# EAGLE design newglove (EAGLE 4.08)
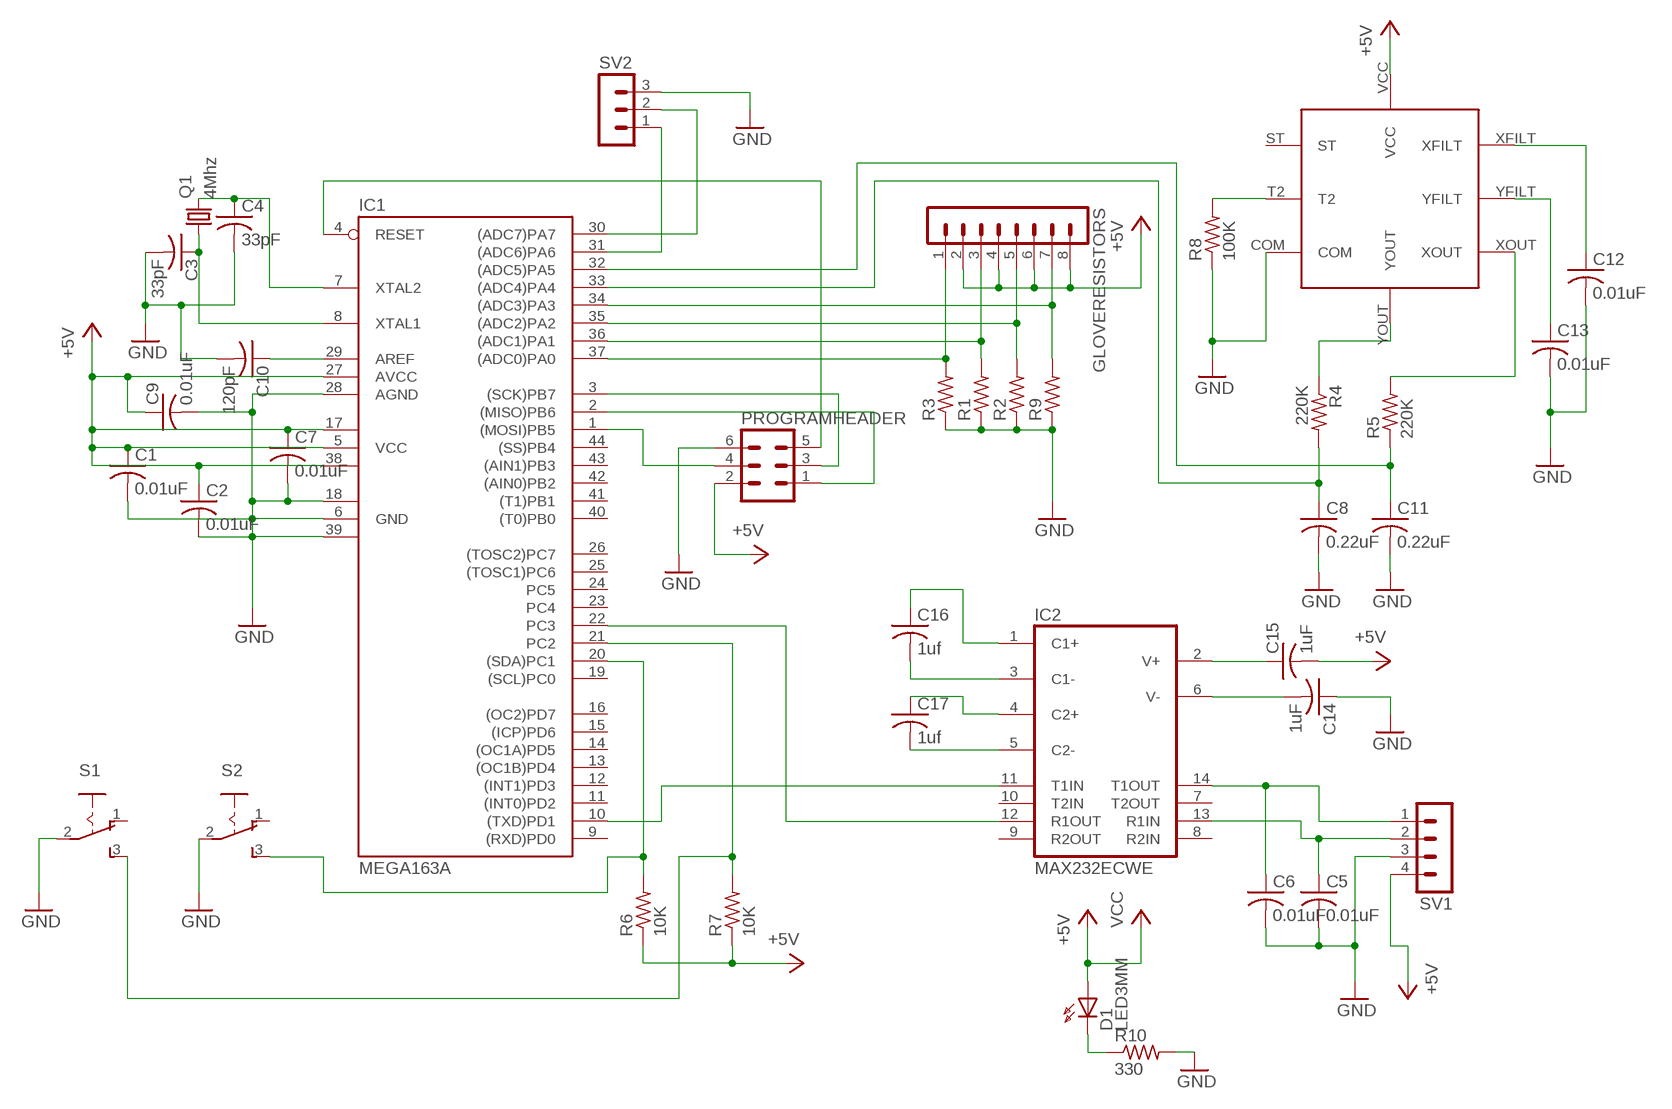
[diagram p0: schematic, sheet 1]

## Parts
C1  0.01uF  C-USC0805  [C0805]
C2  0.01uF  C-USC0805  [C0805]
C3  33pF  C-USC0805  [C0805]
C4  33pF  C-USC0805  [C0805]
C5  0.01uF  C-USC0805  [C0805]
C6  0.01uF  C-USC0805  [C0805]
C7  0.01uF  C-USC0805  [C0805]
C8  0.22uF  C-USC0805  [C0805]
C9  0.01uF  C-USC0805  [C0805]
C10  120pF  C-USC0805  [C0805]
C11  0.22uF  C-USC0805  [C0805]
C12  0.01uF  C-USC0805  [C0805]
C13  0.01uF  C-USC0805  [C0805]
C14  1uF  C-USC0805  [C0805]
C15  1uF  C-USC0805  [C0805]
C16  1uf  C-USC0805  [C0805]
C17  1uf  C-USC0805  [C0805]
D1  LED3MM  [LED3MM]
GLOVERESISTORS  MA08-1  [MA08-1]
IC1  MEGA163A  [TQFP44]
IC2  MAX232ECWE  [SO16L]
PROGRAMHEADER  MA03-2  [MA03-2]
Q1  4Mhz  HC49/S  [HC49/S]
R1  R-US_R0805  [R0805]
R2  R-US_R0805  [R0805]
R3  R-US_R0805  [R0805]
R4  220K  R-US_R0805  [R0805]
R5  220K  R-US_R0805  [R0805]
R6  10K  R-US_R0805  [R0805]
R7  10K  R-US_R0805  [R0805]
R8  100K  R-US_R0805  [R0805]
R9  R-US_R0805  [R0805]
R10  330  R-US_M0805  [M0805]
S1  255SB  [255SB]
S2  255SB  [255SB]
SV1  MA04-1  [MA04-1]
SV2  MA03-1  [MA03-1]
U$1  ADXL202E  [ADXL202E]

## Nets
+5V: C1.1 C2.1 C7.1 C9.1 C15.2 D1.A GLOVERESISTORS.2 GLOVERESISTORS.4 GLOVERESISTORS.6 GLOVERESISTORS.8 IC1.5(VCC) IC1.17(VCC1) IC1.27(AVCC) IC1.38(VCC2) PROGRAMHEADER.2 R6.1 R7.1 SV1.4 U$1.VCC ; supply symbol labelled VCC
GND: C1.2 C2.2 C3.2 C4.2 C5.2 C6.2 C7.2 C8.2 C9.2 C10.2 C11.2 C12.2 C13.2 C14.1 IC1.6(GND) IC1.18(GND1) IC1.28(AGND) IC1.39(GND2) PROGRAMHEADER.6 R1.1 R2.1 R3.1 R8.1 R9.1 R10.2 S1.2(P) S2.2(P) SV1.3 SV2.3 U$1.COM
N$2: IC1.22(PC3) IC2.12(R1OUT)
N$3: IC1.4(RESET) PROGRAMHEADER.5
N$4: IC1.3((SCK)PB7) PROGRAMHEADER.3
N$5: IC1.2((MISO)PB6) PROGRAMHEADER.1
N$6: IC1.1((MOSI)PB5) PROGRAMHEADER.4
N$8: C10.1 IC1.29(AREF)
N$9: C15.1 IC2.2(V+)
N$10: C4.1 IC1.7(XTAL2) Q1.2
N$11: C3.1 IC1.8(XTAL1) Q1.1
N$12: C14.2 IC2.6(V-)
N$13: IC1.31((ADC6)PA6) SV2.1
N$14: C17.2 IC2.5(C2-)
N$15: C17.1 IC2.4(C2+)
N$16: C16.2 IC2.3(C1-)
N$17: C16.1 IC2.1(C1+)
N$18: C6.1 IC2.14(T1OUT) SV1.1
N$19: C5.1 IC2.13(R1IN) SV1.2
N$20: IC1.10((TXD)PD1) IC2.11(T1IN)
N$21: IC1.21(PC2) R7.2 S1.3(S)
N$22: GLOVERESISTORS.1 IC1.37((ADC0)PA0) R3.2
N$23: IC1.30((ADC7)PA7) SV2.2
N$24: R8.2 U$1.T2
N$29: GLOVERESISTORS.3 IC1.36((ADC1)PA1) R1.2
N$30: GLOVERESISTORS.5 IC1.35((ADC2)PA2) R2.2
N$31: GLOVERESISTORS.7 IC1.34((ADC3)PA3) R9.2
N$32: C8.1 IC1.33((ADC4)PA4) R4.2
N$33: C11.1 IC1.32((ADC5)PA5) R5.1
N$34: C12.1 U$1.XFILT
N$35: C13.1 U$1.YFILT
N$36: D1.K(C) R10.1
N$38: R5.2 U$1.XOUT
N$39: R4.1 U$1.YOUT
N$40: IC1.20((SDA)PC1) R6.2 S2.3(S)
Unconnected: IC1.9((RXD)PD0) IC1.11((INT0)PD2) IC1.12((INT1)PD3) IC1.13((OC1B)PD4) IC1.14((OC1A)PD5) IC1.15((ICP)PD6) IC1.16((OC2)PD7) IC1.19((SCL)PC0) IC1.23(PC4) IC1.24(PC5) IC1.25((TOSC1)PC6) IC1.26((TOSC2)PC7) IC1.40((T0)PB0) IC1.41((T1)PB1) IC1.42((AIN0)PB2) IC1.43((AIN1)PB3) IC1.44((SS)PB4) IC2.7(T2OUT) IC2.8(R2IN) IC2.9(R2OUT) IC2.10(T2IN) S1.1(O) S2.1(O) U$1.ST

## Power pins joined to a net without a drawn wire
+5V: IC2.16(VCC)
GND: IC2.15(GND)

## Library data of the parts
C1-C17 = rcl:C-US: CAPACITOR, American symbol
D1 = led:LED3MM: LED
GLOVERESISTORS = con-lstb:MA08-1: PIN HEADER
IC1 = atmel:MEGA163*: MICROCONTROLLER 16 Kbytes FLASH, 1 Kbytes EEPROM 1 Kbytes SRAM UART 8-channel 10 bit ADC hardware multiplier
IC2 = maxim:MAX232ECWE: RS232 TRANSEIVER
PROGRAMHEADER = con-lstb:MA03-2: PIN HEADER
Q1 = crystal:HC49/S: CRYSTAL
R1-R10 = rcl:R-US_: RESISTOR, American symbol
S1 S2 = switch:255SB: SLIDING SWITCH distributor Buerklin, 11G810
SV1 = con-lstb:MA04-1: PIN HEADER
SV2 = con-lstb:MA03-1: PIN HEADER
U$1 = Accelero:ADXL202E: ADXL202E Analog Devices Accelerometer Ceramic Leadless Package

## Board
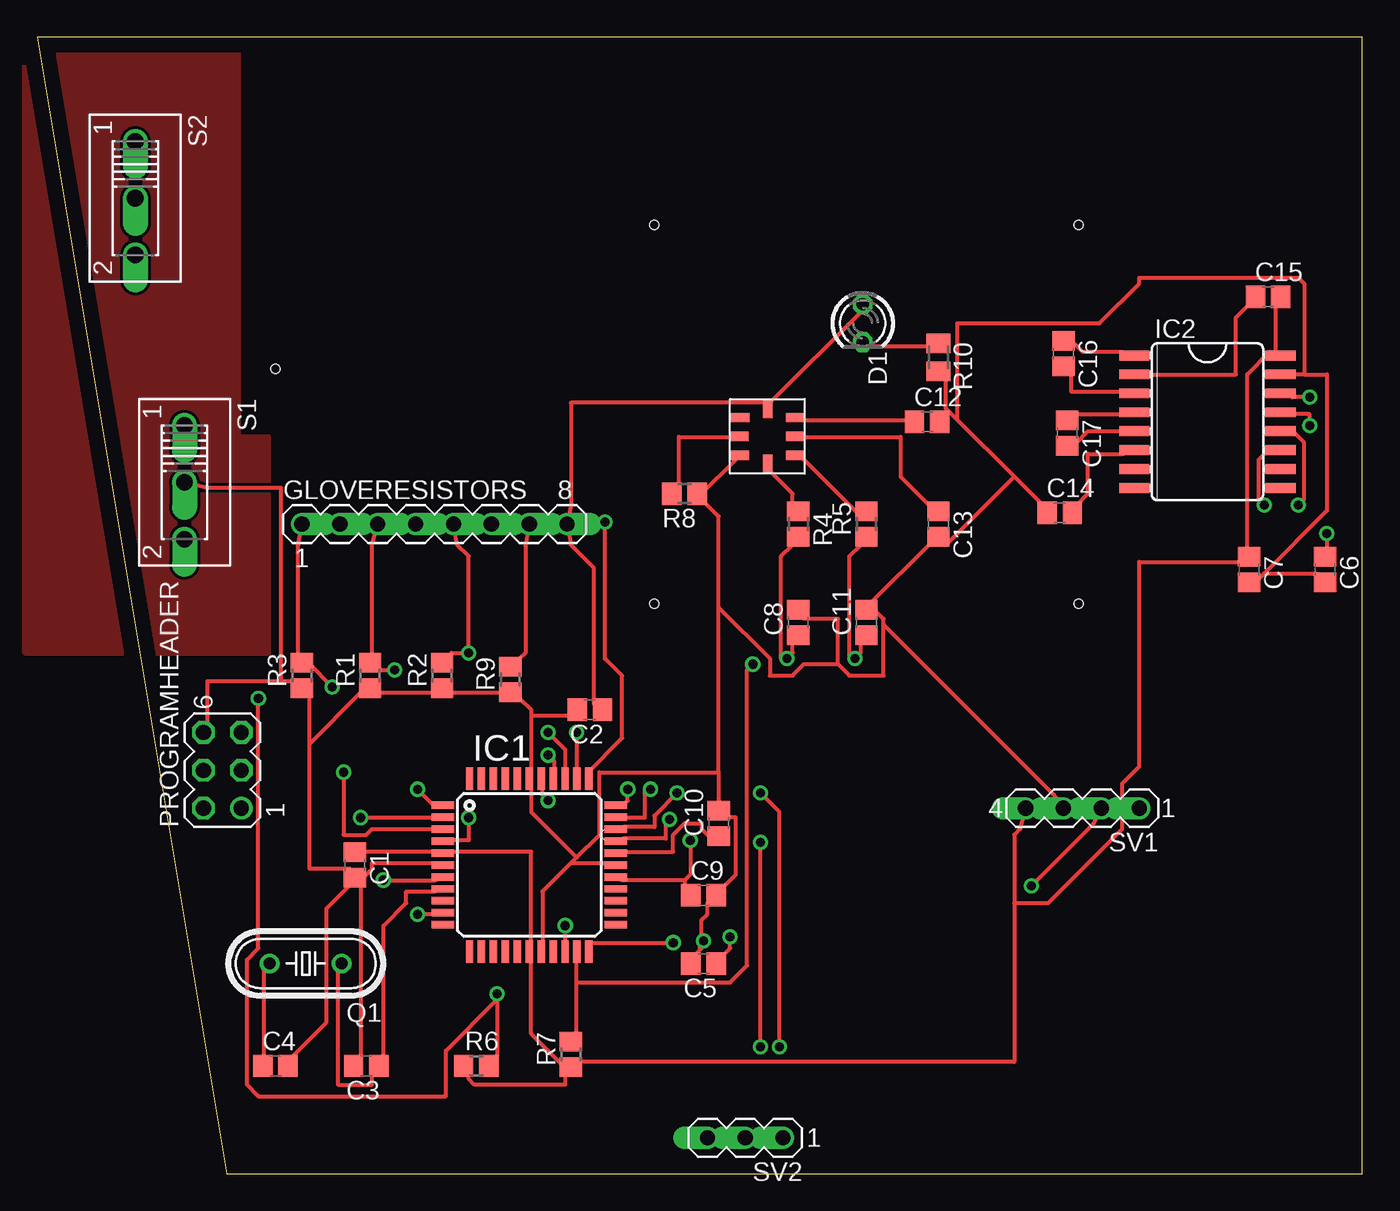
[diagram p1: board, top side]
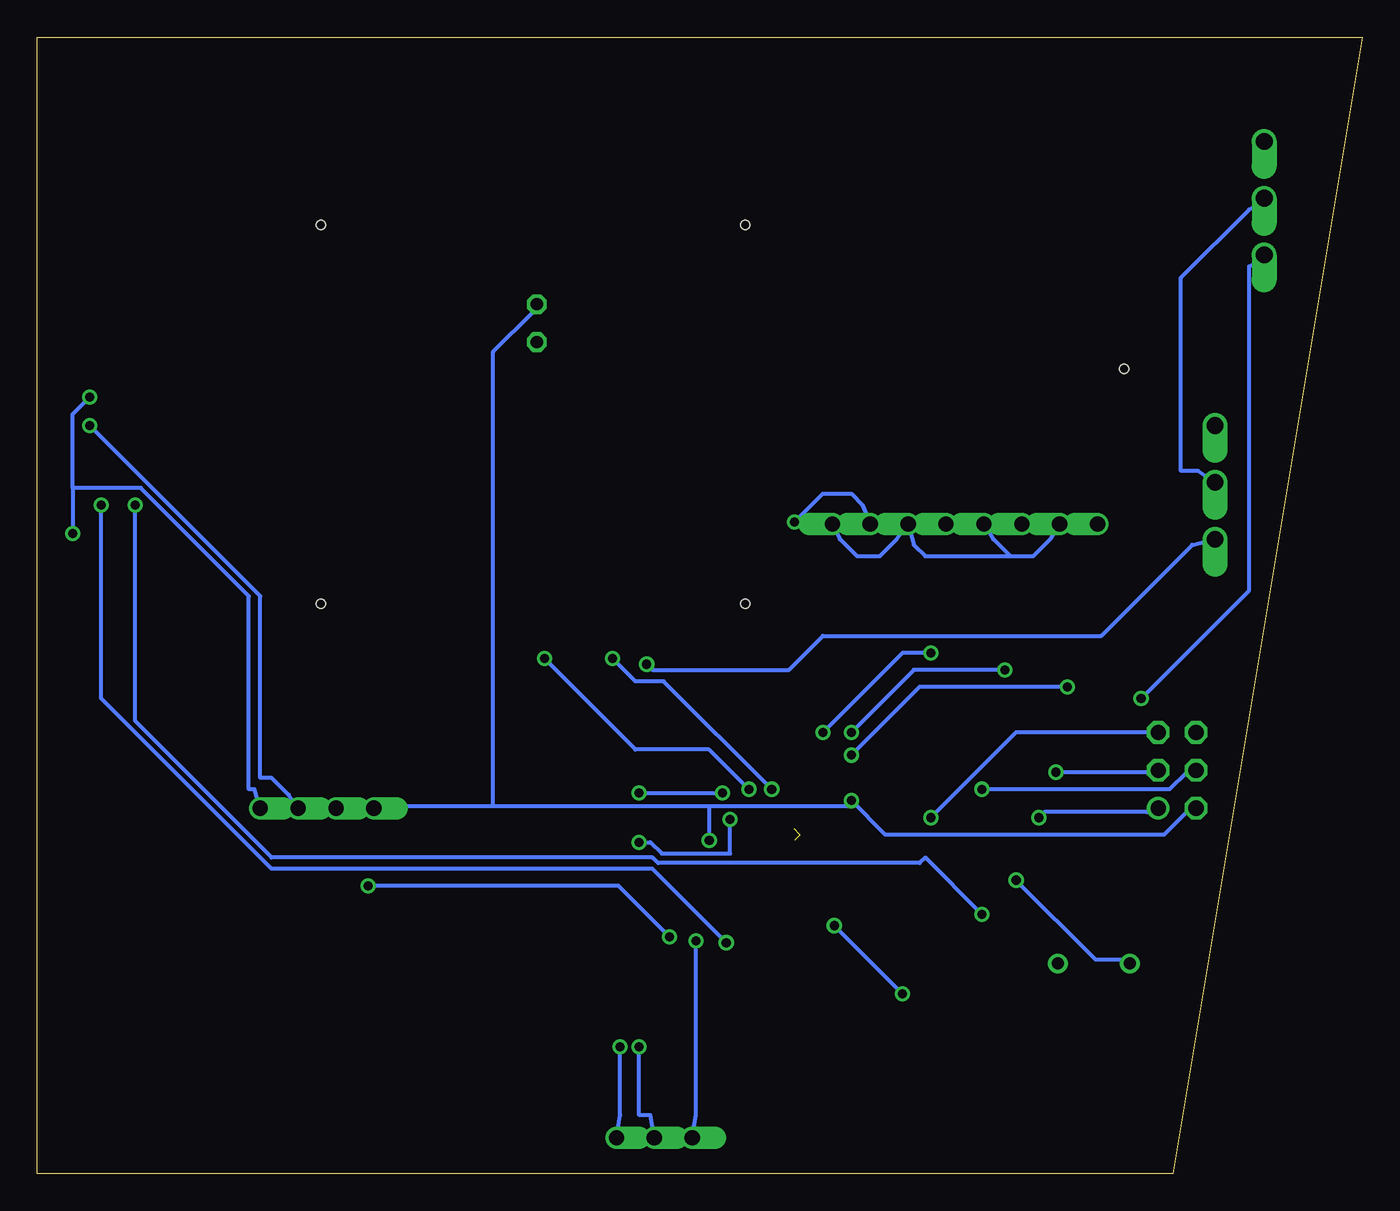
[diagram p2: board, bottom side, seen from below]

Size 88.82 x 76.19 mm. Coordinates in mm from the lower left corner, seen from the top.
Outline: 12.7,0 88.82,0 88.82,76.19 0,76.19 12.7,0
Copper layers used: Top, Bottom
Holes 0.61 mm at 69.81,63.62 69.81,38.22 41.36,38.22 41.36,63.62 15.96,53.97
tKeepout: area 61.7,1.1 to 87.6,19.9; area 12.2,3.9 to 28.4,19.9
bKeepout: area 61.9,1.1 to 87.6,19.9; area 12.2,3.7 to 28.4,19.9
tRestrict: area 38.8,34.4 to 45.4,40.8; area 13.9,50.7 to 19,56.5; area 66.8,35.2 to 73.4,40.8; area 66.5,60.1 to 73.6,66.7; area 37.3,60.1 to 45.2,66.7
bRestrict: area 38.6,34.2 to 45.7,40.8; area 13.9,50.7 to 18.8,56.3; area 37.3,60.1 to 45.2,66.7; area 66.5,60.1 to 73.6,66.7; area 66.8,35.2 to 73.4,40.8

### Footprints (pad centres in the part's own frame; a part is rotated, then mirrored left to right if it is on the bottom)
C0805 = smd 1.3 x 1.5: 1 -0.85,0; 2 0.85,0
LED3MM = drill 0.813 octagon: A -1.27,0; K 1.27,0
MA08-1 = drill 1.016 offset: 1 -8.89,0; 2 -6.35,0; 3 -3.81,0; 4 -1.27,0; 5 1.27,0; 6 3.81,0; 7 6.35,0; 8 8.89,0
TQFP44 = smd 1.5 x 0.5: 1 -5.8,4; 2 -5.8,3.2; 3 -5.8,2.4; 4 -5.8,1.6; 5 -5.8,0.8; 6 -5.8,0; 7 -5.8,-0.8; 8 -5.8,-1.6; 9 -5.8,-2.4; 10 -5.8,-3.2; 11 -5.8,-4; 23 5.8,-4; 24 5.8,-3.2; 25 5.8,-2.4; 26 5.8,-1.6; 27 5.8,-0.8; 28 5.8,0; 29 5.8,0.8; 30 5.8,1.6; 31 5.8,2.4; 32 5.8,3.2; 33 5.8,4 | smd 0.5 x 1.5: 12 -4,-5.8; 13 -3.2,-5.8; 14 -2.4,-5.8; 15 -1.6,-5.8; 16 -0.8,-5.8; 17 0,-5.8; 18 0.8,-5.8; 19 1.6,-5.8; 20 2.4,-5.8; 21 3.2,-5.8; 22 4,-5.8; 34 4,5.8; 35 3.2,5.8; 36 2.4,5.8; 37 1.6,5.8; 38 0.8,5.8; 39 0,5.8; 40 -0.8,5.8; 41 -1.6,5.8; 42 -2.4,5.8; 43 -3.2,5.8; 44 -4,5.8
SO16L = smd 0.66 x 2.032: 1 -4.445,-4.902; 2 -3.175,-4.902; 3 -1.905,-4.902; 4 -0.635,-4.902; 5 0.635,-4.902; 6 1.905,-4.902; 7 3.175,-4.902; 8 4.445,-4.902; 9 4.445,4.902; 10 3.175,4.902; 11 1.905,4.902; 12 0.635,4.902; 13 -0.635,4.902; 14 -1.905,4.902; 15 -3.175,4.902; 16 -4.445,4.902
MA03-2 = drill 1.016 round: 1 -2.54,-1.27 | drill 1.016 octagon: 2 -2.54,1.27; 3 0,-1.27; 4 0,1.27; 5 2.54,-1.27; 6 2.54,1.27
HC49/S = drill 0.813 round: 1 -2.413,0; 2 2.413,0
R0805 = smd 1.3 x 1.5: 1 -0.85,0; 2 0.85,0
M0805 = smd 1.3 x 1.6: 1 -0.95,0; 2 0.95,0
255SB = drill 1.118 offset: 1 -3.81,0; 2 0,0; 3 3.81,0
MA04-1 = drill 1.016 offset: 1 -3.81,0; 2 -1.27,0; 3 1.27,0; 4 3.81,0
MA03-1 = drill 1.016 offset: 1 -2.54,0; 2 0,0; 3 2.54,0
ADXL202E = smd 1.27 x 0.635: COM 0.635,-3.785; ST 0.66,-1.245; T2 0.61,-2.515; XFILT 4.369,-1.245; XOUT 4.369,-3.785; YFILT 4.369,-2.515 | smd 0.635 x 1.27: VCC 2.515,-0.635; YOUT 2.515,-4.369

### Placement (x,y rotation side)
C1  21.3,20.7 270 top
C2  37.05,31.11 180 top
C3  22.06,7.23 180 top
C4  15.96,7.23 0 top
C5  44.67,14.09 180 top
C6  86.32,40.51 270 top
C7  81.24,40.51 270 top
C8  51.02,36.95 90 top
C9  44.67,18.66 0 top
C10  45.68,23.49 90 top
C11  55.59,36.95 90 top
C12  59.65,50.41 0 top
C13  60.41,43.56 270 top
C14  68.54,44.32 0 top
C15  82.51,58.8 0 top
C16  68.8,54.99 270 top
C17  69.05,49.65 270 top
D1  55.33,57.02 270 top
GLOVERESISTORS  26.63,43.56 0 top
IC1  32.98,20.7 0 top
IC2  78.45,50.41 270 top
PROGRAMHEADER  12.41,27.05 90 top
Q1  18,14.09 180 top
R1  22.31,33.4 90 top
R2  27.14,33.4 90 top
R3  17.74,33.4 90 top
R4  51.02,43.56 270 top
R5  55.59,43.56 90 top
R6  29.43,7.23 0 top
R7  35.78,8 90 top
R8  43.4,45.59 180 top
R9  31.71,33.14 90 top
R10  60.41,54.73 270 top
S1  9.87,46.35 270 top
S2  6.57,65.4 270 top
SV1  70.07,24.51 180 top
SV2  47.46,2.41 180 top
U$1  46.44,51.94 0 top

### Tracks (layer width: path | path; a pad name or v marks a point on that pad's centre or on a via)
+5V  (via drill 0.61)
  Top 0.254: D1.A 55.21,57.78 49.11,51.68 U$1.VCC 48.73,51.68 35.78,51.68 35.78,44.83 GLOVERESISTORS.8 35.78,42.16 37.3,40.64 37.3,31.49 C2.1 | C1.1 21.68,21.58 26.63,21.58 IC1.5 27.78,21.58 33.11,21.58 33.11,15.49 IC1.17 33.11,14.35 33.11,9.39 35.39,7.11 R7.1 | R6.1 28.92,6.73 28.92,6.34 29.3,5.96 35.39,5.96 35.39,6.73 R7.1 | C15.2 83.02,58.16 83.02,55.11 IC2.16 82.64,55.11 81.11,53.59 81.11,41.78 C7.1 80.73,41.02 73.88,41.02 73.88,27.3 72.73,26.16 72.73,23.11 67.78,18.16 65.49,18.16 | 43.4,19.68 43.4,19.3 C9.1 | v34.25,25.01 33.87,25.39 33.87,25.78 IC1.38 | 43.4,19.68 43.78,20.06 v43.78,22.35 | 65.49,18.16 65.49,22.73 65.88,23.11 SV1.4 | 65.49,18.16 65.49,7.49 36.16,7.49 R7.1 | 43.4,19.68 39.2,19.68 IC1.27
  Bottom 0.254: 23.58,41.4 22.06,41.4 20.92,42.54 GLOVERESISTORS.2 | 23.58,41.4 24.73,42.54 GLOVERESISTORS.4 | 23.58,41.4 29.3,41.4 30.06,42.16 GLOVERESISTORS.6 31.2,42.54 32.35,41.4 33.87,41.4 35.01,42.54 GLOVERESISTORS.8 | PROGRAMHEADER.2 11.77,24.25 13.3,22.73 31.97,22.73 v34.25,25.01 34.25,24.63 43.78,24.63 | 43.78,24.63 58.25,24.63 | 58.25,24.63 65.88,24.63 SV1.4 | 43.78,24.63 v43.78,22.35 | 58.25,24.63 58.25,55.11 55.59,57.78 D1.A
GND  (via drill 0.61)  (2 unrouted)
  Top 0.254: 84.92,53.59 86.45,53.59 86.45,44.45 82.26,40.25 | 82.26,40.25 81.88,39.87 C7.2 | 84.92,53.59 IC2.15 | 82.26,40.25 85.69,40.25 C6.2 | 61.68,50.54 60.92,51.3 | 65.49,46.73 61.68,50.54 | 65.49,46.73 67.4,44.83 C14.1 | 60.92,51.3 60.92,53.21 R10.2 | 60.92,51.3 60.92,50.92 C12.2 | 53.68,34.16 53.68,37.21 51.4,37.21 C8.2 | 53.68,34.16 54.44,33.4 56.73,33.4 56.73,36.83 | 56.73,36.83 56.73,37.21 55.97,37.97 C11.2 55.97,38.35 59.78,42.16 C13.2 60.92,42.16 65.49,46.73 | 56.73,36.83 68.16,25.39 SV1.3 | 84.92,53.59 84.92,59.69 84.54,60.07 73.88,60.07 73.88,59.69 71.21,57.02 61.68,57.02 61.68,50.54 | U$1.COM 46.83,47.87 44.54,45.59 R8.1 44.54,45.21 45.68,44.06 45.68,37.97 | 44.47,15.04 44.54,15.11 44.54,17.01 44.92,17.39 44.92,18.16 C9.2 46.06,19.3 46.83,20.06 46.83,23.87 46.06,23.87 C10.2 45.68,24.63 45.68,26.92 | 44.47,15.04 44.16,14.73 C5.2 | 45.68,26.92 45.68,37.97 | 36.16,21.2 37.68,22.73 37.68,26.92 45.68,26.92 | 36.16,21.2 35.78,20.82 | 35.78,20.82 33.87,18.92 33.87,15.49 IC1.18 | 35.78,20.82 38.06,20.82 IC1.28 | 33.11,30.73 33.11,31.11 32.35,31.87 R9.1 31.2,32.25 27.78,32.25 R2.1 26.63,32.25 22.82,32.25 R1.1 21.68,32.25 18.25,28.82 | 33.11,30.73 33.11,26.92 IC1.39 33.11,25.78 33.11,24.25 36.16,21.2 | 33.11,30.73 35.78,30.73 C2.2 | IC1.6 26.63,20.82 22.44,20.82 22.44,20.44 21.68,19.68 C1.2 | C4.2 17.11,7.87 19.39,10.16 19.39,17.77 20.92,19.3 C1.2 | C3.2 21.68,7.87 21.68,19.3 C1.2 | 16.34,33.02 11.39,33.02 11.39,30.35 PROGRAMHEADER.6 | 16.34,33.02 17.11,33.02 R3.1 18.25,32.25 18.25,28.82 | 16.34,33.02 16.34,45.97 11.39,45.97 S1.2 | 18.25,28.82 18.25,20.44 20.92,20.44 C1.2 | 53.68,34.16 51.4,34.16 50.64,33.4 49.11,33.4 49.11,34.54 45.68,37.97
  Top 0.254: v44.67,15.62 44.41,15.36 44.41,15.11 44.47,15.04
  Bottom 0.254: S2.2 7.58,64.64 12.15,60.07 12.15,47.11 11.01,47.11 S1.2 | v44.67,15.62 44.67,3.93 SV2.3
N$1
  pour Top: -0.8,75.81 13.42,75.81 13.42,53.72 -0.8,53.72 -0.8,61.59
N$2  (via drill 0.61)
  Top 0.254: v42.63,15.49 36.92,15.49 IC1.22 | v84.54,44.83 84.92,45.21 84.92,49.02 84.16,49.78 IC2.12
  Bottom 0.254: v42.63,15.49 47.59,20.44 73.11,20.44 84.54,31.87 v84.54,44.83
N$3  (via drill 0.61)
  Top 0.254: v28.92,23.87 28.92,22.35 27.78,22.35 IC1.4
  Bottom 0.254: v28.92,23.87 23.2,29.59 PROGRAMHEADER.5
N$4  (via drill 0.61)
  Top 0.254: v20.54,26.92 20.54,22.73 22.06,22.73 22.44,23.11 26.63,23.11 IC1.3
  Bottom 0.254: v20.54,26.92 14.44,26.92 PROGRAMHEADER.3
N$5  (via drill 0.61)
  Top 0.254: v21.68,23.87 26.63,23.87 IC1.2
  Bottom 0.254: v21.68,23.87 21.3,24.25 14.44,24.25 PROGRAMHEADER.1
N$6  (via drill 0.61)
  Top 0.254: v25.49,25.78 26.63,24.63 IC1.1
  Bottom 0.254: v25.49,25.78 12.92,25.78 11.77,26.92 PROGRAMHEADER.4
N$7
  pour Top: -0.8,53.97 13.42,53.97 13.42,49.4 15.46,49.4 15.46,34.92 -0.8,34.92
N$8
  Top 0.254: IC1.29 39.2,21.58 42.63,21.58 42.63,22.73 43.4,23.49 44.54,23.49 44.54,23.11 45.3,22.35 C10.1
N$9
  Top 0.254: IC2.2 80.35,53.59 80.35,57.4 81.11,58.16 C15.1
N$10  (via drill 0.61)
  Top 0.254: v23.2,19.68 26.63,19.68 IC1.7 | C4.1 15.2,7.87 15.2,13.58 Q1.2
  Bottom 0.254: v23.2,19.68 17.87,14.35 15.96,14.35 Q1.2
N$11
  Top 0.254: IC1.8 26.63,18.92 24.73,18.92 24.73,18.16 23.2,16.63 23.2,7.87 C3.1 22.44,6.73 22.44,5.96 20.16,5.96 20.16,13.58 Q1.1
N$12
  Top 0.254: IC2.6 72.73,48.26 70.45,48.26 70.45,45.59 69.69,44.83 C14.2
N$13  (via drill 0.61)
  Top 0.254: v42.89,25.52 41.36,24 41.36,23.24 39.33,23.24 IC1.31 | v48.48,25.52 49.75,24.25 v49.75,8.5
  Bottom 0.254: v48.48,25.52 v42.89,25.52 | v49.75,8.5 49.75,3.93 SV2.1
N$14
  Top 0.254: IC2.5 70.45,49.78 69.69,49.02 C17.2
N$15
  Top 0.254: IC2.4 72.73,50.92 69.69,50.92 C17.1
N$16
  Top 0.254: IC2.3 72.73,52.45 69.3,52.45 69.3,53.59 C16.2
N$17
  Top 0.254: IC2.1 72.73,55.11 70.07,55.11 69.3,55.88 C16.1
N$18  (via drill 0.61)
  Top 0.254: v85.31,52.07 84.16,52.07 IC2.14 | v86.45,42.92 86.45,41.78 C6.1
  Bottom 0.254: v85.31,52.07 86.45,50.92 86.45,45.97 | 86.45,45.97 81.88,45.97 74.64,38.73 74.64,25.78 74.26,25.78 SV1.1 | 86.45,45.97 v86.45,42.92
N$19  (via drill 0.61)
  Top 0.254: v85.31,50.16 85.31,50.92 84.16,50.92 IC2.13 | v46.44,15.87 46.44,15.11 46.06,14.73 C5.1 | v66.64,19.3 70.83,23.49 SV1.2
  Bottom 0.254: v85.31,50.16 73.88,38.73 73.88,26.54 73.11,26.54 71.97,25.39 SV1.2 | v46.44,15.87 49.87,19.3 v66.64,19.3
N$20  (via drill 0.61)
  Top 0.254: v25.49,17.39 26.63,17.39 IC1.10 | v82.26,44.83 81.88,45.21 81.88,47.87 82.64,48.64 IC2.11
  Bottom 0.254: v25.49,17.39 29.3,21.2 29.68,20.82 47.21,20.82 47.59,21.2 73.11,21.2 82.26,30.35 v82.26,44.83
N$21  (via drill 0.61)
  Top 0.254: 36.16,12.82 36.16,9.39 R7.2 | 36.16,12.82 36.16,14.35 IC1.21 | v47.97,34.16 47.59,33.78 47.59,13.97 46.44,12.82 36.16,12.82
  Bottom 0.254: v47.97,34.16 47.59,33.78 38.44,33.78 36.16,36.06 17.49,36.06 11.39,42.16 S1.3
N$22  (via drill 0.61)
  Top 0.254: v34.25,28.06 34.63,27.68 34.63,26.92 IC1.37 | v19.77,32.63 18.25,34.16 R3.2 17.49,34.54 17.49,42.16 GLOVERESISTORS.1
  Bottom 0.254: v34.25,28.06 29.68,32.63 v19.77,32.63
N$23  (via drill 0.61)
  Top 0.254: v42.38,23.74 42.13,23.49 42.13,22.47 39.33,22.47 IC1.30 | v48.48,8.5 v48.48,22.22
  Bottom 0.254: v42.38,23.74 42.38,21.46 46.95,21.46 47.71,22.22 v48.48,22.22 | v48.48,8.5 48.48,3.93 47.71,3.93 SV2.2
N$24
  Top 0.254: U$1.T2 46.44,49.4 43.02,49.4 43.02,45.97 R8.2
N$29  (via drill 0.61)
  Top 0.254: v34.25,29.59 35.39,28.44 35.39,26.92 IC1.36 | v23.96,33.78 22.82,33.78 R1.2 22.44,34.54 22.44,42.16 GLOVERESISTORS.3
  Bottom 0.254: v34.25,29.59 30.06,33.78 v23.96,33.78
N$30  (via drill 0.61)
  Top 0.254: v36.16,29.59 36.16,26.92 IC1.35 | R2.2 27.78,34.54 27.78,34.92 v28.92,34.92 28.92,41.4 28.16,42.16 GLOVERESISTORS.5
  Bottom 0.254: v36.16,29.59 30.82,34.92 v28.92,34.92
N$31  (via drill 0.61)
  Top 0.254: v38.06,43.68 38.06,34.54 39.2,33.4 39.2,29.2 36.92,26.92 IC1.34 | R9.2 32.35,34.54 32.73,34.92 32.73,42.16 GLOVERESISTORS.7
  Bottom 0.254: v38.06,43.68 36.16,45.59 34.25,45.59 33.49,44.83 GLOVERESISTORS.7
N$32  (via drill 0.61)
  Top 0.254: v39.59,25.78 39.59,25.01 39.2,24.63 IC1.33 | C8.1 50.64,35.68 50.64,34.92 v50.25,34.54 49.87,34.54 49.87,41.4 50.64,42.16 R4.2
  Bottom 0.254: v39.59,25.78 46.83,33.02 48.73,33.02 v50.25,34.54
N$33  (via drill 0.61)
  Top 0.254: C11.1 55.21,35.68 55.21,34.92 v54.83,34.54 54.44,34.54 54.44,41.4 55.21,42.16 R5.1 | IC1.32 39.2,23.87 40.73,23.87 40.73,25.78 v41.11,25.78
  Bottom 0.254: v41.11,25.78 43.78,28.44 48.73,28.44 v54.83,34.54
N$34
  Top 0.254: U$1.XFILT 51.4,50.54 58.25,50.54 C12.1
N$35
  Top 0.254: U$1.YFILT 51.4,49.4 57.87,49.4 57.87,46.73 59.78,44.83 C13.1
N$36
  Top 0.254: D1.K 55.97,55.49 59.78,55.49 R10.1
N$38
  Top 0.254: U$1.XOUT 51.4,47.87 55.21,44.06 R5.2
N$39
  Top 0.254: U$1.YOUT 49.11,47.11 50.64,45.59 50.64,44.83 R4.1
N$40  (via drill 0.61)
  Top 0.254: v35.39,16.63 35.39,15.49 IC1.20 | 30.82,11.68 30.82,7.87 R6.2 | v14.82,31.87 14.82,15.11 14.06,14.35 14.06,5.96 14.82,5.2 27.39,5.2 27.39,8.25 30.82,11.68 | 30.82,11.68 v30.82,12.06
  Bottom 0.254: v30.82,12.06 v35.39,16.63 | v14.82,31.87 7.58,39.11 7.58,60.83 S2.3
